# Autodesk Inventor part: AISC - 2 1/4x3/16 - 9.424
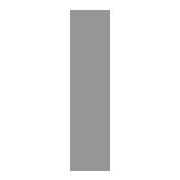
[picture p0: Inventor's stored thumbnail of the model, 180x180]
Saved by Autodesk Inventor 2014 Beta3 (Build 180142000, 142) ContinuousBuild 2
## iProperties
_CCFamilyMember: 147
_CCFamilyDisplayName: ANSI AISC (Rectangular) - Flat Bar Steel
_FrameMemberDoc: Frame Member File
_Version: 15.0.0
_GetPNFromCC: 1
Created: 2010-11
Part Number: AISC - 2 1/4x3/16 - 9.424
Material: Steel, Mild
Description: Flat Bar Steel
Document SubType Name: Modeling
Standard: ANSI
Designer: Beta-8540w
Standards Organization: ANSI
Language: en-US
Size Designation: 2 1/4x3/16
Categories: <MemberInstance><Categories><Category DisplayName="Structural Shapes" InternalName="089c4875-fa83-4c05-b084-43b9cc11f5ed" Mnemonic="GRDR"><CategoryParameter Dis
Stock Number: 2 1/4x3/16
Density: 7.86 g/cm^3
Appearance: Steel
IsCustomPart: 1
G_L: 9.424 in
G_W: 0.188 in
G_H: 2.250 in
Author: Beta-8540w
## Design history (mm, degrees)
node "Start plane"
node "End plane"
node "Driven Length"
  sketch "Sketch3"
    geometry: L1 (0, 0)-(10, 0) reference
    constraints: 2 end point, 1 horizontal
  workplane "Work Plane3"
  sketch "Sketch4"
    geometry: L1 (-2, 0)-(12, 0) reference; L2 (-40.005, 239.358)-(40.005, 239.358) reference
    dimensions: "d9" = 239.35777 distance between parallel lines of L1 L2 (derived)
sketch "Sweep Path"
  geometry: L1 through (25.4, 40.279) direction (1, 0); L2 through (112.121, 127) direction (1, 0); 8 other entities
  constraints: 10 horizontal
node "Orientation Work Plane"
feature "Body" dims "d10" = 0
body "Solid1"
sketch "Sketch"
  geometry: L1 (2.381, -28.575)-(-2.381, -28.575); L2 (-2.381, -28.575)-(-2.381, 28.575); L3 (-2.381, 28.575)-(2.381, 28.575); L4 (2.381, 28.575)-(2.381, -28.575); L5 (-6, 0)-(8, 0); L6 (0, -30)-(0, 40); L7 (0, 54)-(0, -44); L8 (-9.2, 0)-(13.2, 0)
  constraints: 16 end point, 2 collinear, 2 parallel, 1 horizontal, 1 perpendicular
  dimensions: "d0" = 57.15 distance between parallel lines of L3 L1 (= G_W); "d1" = 4.7625 distance between parallel lines of L4 L2 (= G_H); "d4" = 2.38125 distance between parallel lines of L6 L4 (= 0.5 x d1); "d5" = 28.575 distance between parallel lines of L5 L3 (= 0.5 x d0)
other parameters: "G_W" = 57.15 [user parameter; used in 1 equation term], "G_H" = 4.7625 [user parameter; used in 1 equation term], "G_L" = 239.35777 (= d9) [user parameter], "G_OFFSET_START" = 0 [user parameter; used in 1 equation term], "G_OFFSET_END" = 0 [user parameter; used in 1 equation term], "d6" = 0 (computed from G_OFFSET_START), "d7" = 239.35777 (= G_OFFSET_END + B_L), "B_L" = 239.35777 [user parameter; used in 1 equation term], "d8" = 90 deg
